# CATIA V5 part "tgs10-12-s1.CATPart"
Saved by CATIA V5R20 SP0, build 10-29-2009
Part number: TGS10-12-S1
Revision: 1
Definition: design
Nomenclature: TGS10-12-S1
Source: made
Description: NOT SPECIFIED
Bounding box of the stored display mesh (mm): x -22 to 0.8, y 0 to 10, z -4 to 4
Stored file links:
  C:\Users\Raffaele\Desktop\3D X SITO CF\I-MOLD\TGS-S1\tgs10-s1.step\tgs10-12-s1.CATPart
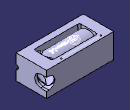
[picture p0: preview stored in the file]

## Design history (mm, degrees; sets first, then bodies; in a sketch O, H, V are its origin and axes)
Set1
  Line1 "LINE #4227": stored without definition
  DatumCurve1 "COMPOSITE_CURVE #4298"
  DatumCurve2 "COMPOSITE_CURVE #4349"
  DatumCurve3 "COMPOSITE_CURVE #4428"
  DatumCurve4 "COMPOSITE_CURVE #4471"
  DatumCurve5 "COMPOSITE_CURVE #4700"
  DatumCurve6 "COMPOSITE_CURVE #4842"
  DatumCurve7 "COMPOSITE_CURVE #4869"
  DatumCurve8 "COMPOSITE_CURVE #4927"
  DatumCurve9 "COMPOSITE_CURVE #4984"
  DatumCurve10 "COMPOSITE_CURVE #5013"
  DatumSurface1 "OPEN_SHELL #4217"
Body1 "MANIFOLD_SOLID_BREP #4218" (main body)
  Solid1: solid without history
